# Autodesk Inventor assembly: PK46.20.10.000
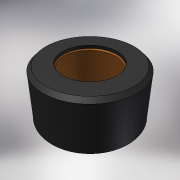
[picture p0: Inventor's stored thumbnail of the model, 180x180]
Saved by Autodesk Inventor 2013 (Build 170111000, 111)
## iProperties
Created: 2012-02
Part Number: PK46.20.10.000
Document SubType Name: Assembly
Designer: tedescj
Author: tedescj
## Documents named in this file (3)
- D:\FrontLoaderVault\Data\Assy, Chassis, Front\PK46.20.10.000.iam
- D:\FrontLoaderVault\Data\Assy, Chassis, Front\PK46.20.11.000.ipt
- D:\FrontLoaderVault\Data\Assy, Chassis, Front\PK46.20.12.000.ipt
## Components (2 placed, 2 different names)
1. PK46.20.11.000:1
2. PK46.20.12.000:1
